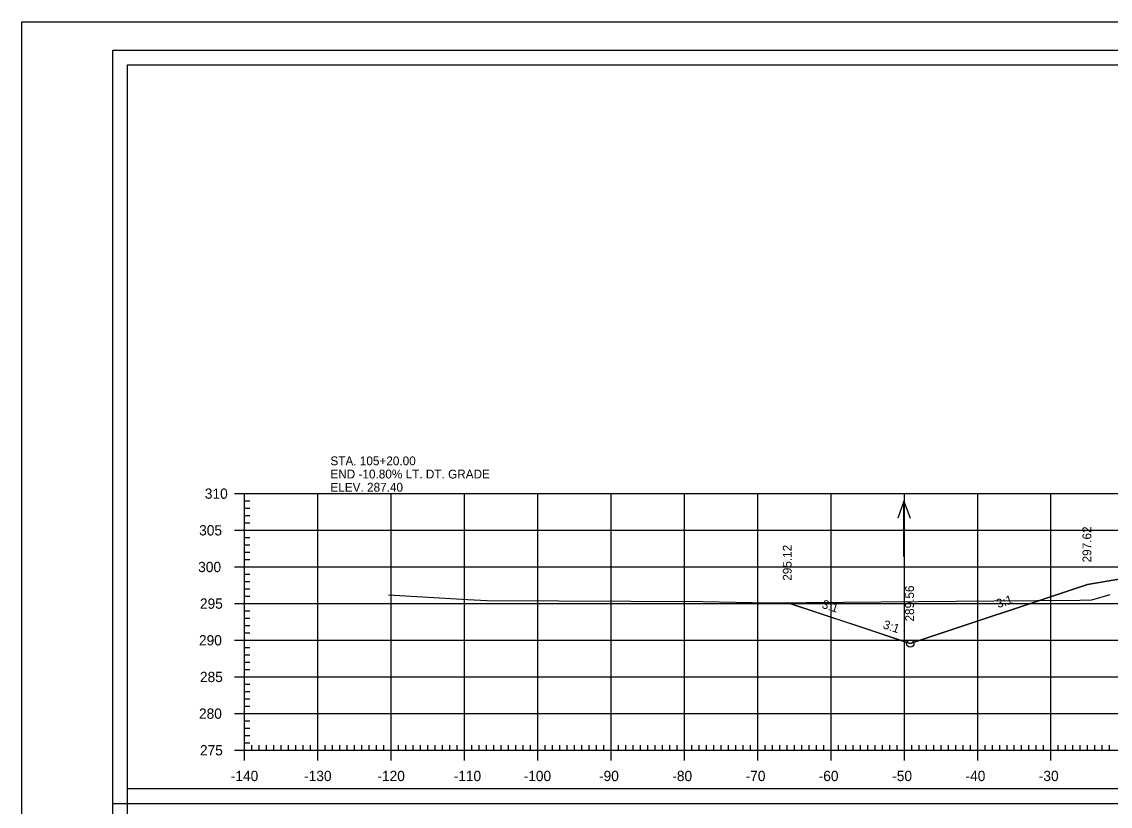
# Model space of a CAD drawing. Extents: x 1368713 to 1370673, y 380279 to 380950.
# Drawn here: x 1369981.9 to 1370130.4, y 380416.8 to 380523.8 of the extents above; entities that cross this region are included whole.
import ezdxf

# ---------------------------------------------------------------- set-up
doc = ezdxf.new("R2010")
doc.units = 0
for name, color, linetype in [('Notes', 7, 'Continuous'), ('R_Alt Surface', 7, 'Continuous'), ('R_Axis', 7, 'Continuous'), ('R_Axis Annot', 7, 'Continuous'), ('R_Border', 7, 'Continuous'), ('R_Border Plan-Plan', 7, 'Continuous'), ('R_Exist Surface', 7, 'Continuous'), ('R_Fin Surface', 7, 'Continuous'), ('R_Grid', 7, 'Continuous'), ('R_No Plot', 7, 'Continuous'), ('R_Water Annot', 7, 'Continuous'), ('R_Xsect Elev', 7, 'Continuous'), ('R_Xsect Slope', 7, 'Continuous')]:
    doc.layers.add(name, color=color, linetype=linetype)

msp = doc.modelspace()

# ---------------------------------------------------------------- linework, layer by layer
at = {"layer": 'R_Alt Surface'}
for points in [[(1370137.28, 380448.71), (1370127.28, 380447.04)], [(1370127.28, 380447.04), (1370103.09, 380438.98)], [(1370103.09, 380438.98), (1370103.09, 380438.98), (1370086.4, 380444.54)]]:
    msp.add_lwpolyline(points, dxfattribs=at)
at = {"layer": 'R_Axis'}
for p, q in [((1370010.88, 380459.42), (1370013.68, 380459.42)), ((1370012.28, 380424.42), (1370012.28, 380459.42)), ((1370012.28, 380458.42), (1370012.98, 380458.42)), ((1370012.28, 380457.42), (1370012.98, 380457.42)), ((1370012.28, 380456.42), (1370012.98, 380456.42)), ((1370012.28, 380455.42), (1370012.98, 380455.42)), ((1370010.88, 380454.42), (1370013.68, 380454.42)), ((1370012.28, 380453.42), (1370012.98, 380453.42)), ((1370012.28, 380452.42), (1370012.98, 380452.42)), ((1370012.28, 380451.42), (1370012.98, 380451.42)), ((1370010.88, 380449.42), (1370013.68, 380449.42)), ((1370012.28, 380450.42), (1370012.98, 380450.42)), ((1370012.28, 380448.42), (1370012.98, 380448.42)), ((1370012.28, 380447.42), (1370012.98, 380447.42)), ((1370012.28, 380446.42), (1370012.98, 380446.42)), ((1370012.28, 380445.42), (1370012.98, 380445.42)), ((1370010.88, 380444.42), (1370013.68, 380444.42)), ((1370012.28, 380443.42), (1370012.98, 380443.42)), ((1370012.28, 380442.42), (1370012.98, 380442.42)), ((1370012.28, 380441.42), (1370012.98, 380441.42)), ((1370010.88, 380439.42), (1370013.68, 380439.42)), ((1370012.28, 380440.42), (1370012.98, 380440.42)), ((1370012.28, 380438.42), (1370012.98, 380438.42)), ((1370012.28, 380437.42), (1370012.98, 380437.42)), ((1370012.28, 380436.42), (1370012.98, 380436.42)), ((1370012.28, 380435.42), (1370012.98, 380435.42)), ((1370010.88, 380434.42), (1370013.68, 380434.42)), ((1370012.28, 380433.42), (1370012.98, 380433.42)), ((1370012.28, 380432.42), (1370012.98, 380432.42)), ((1370012.28, 380431.42), (1370012.98, 380431.42)), ((1370012.28, 380430.42), (1370012.98, 380430.42)), ((1370010.88, 380429.42), (1370013.68, 380429.42)), ((1370012.28, 380428.42), (1370012.98, 380428.42)), ((1370012.28, 380427.42), (1370012.98, 380427.42)), ((1370012.28, 380426.42), (1370012.98, 380426.42)), ((1370012.28, 380423.02), (1370012.28, 380425.82)), ((1370022.28, 380423.02), (1370022.28, 380425.82)), ((1370032.28, 380423.02), (1370032.28, 380425.82)), ((1370042.28, 380423.02), (1370042.28, 380425.82)), ((1370052.28, 380423.02), (1370052.28, 380425.82)), ((1370062.28, 380423.02), (1370062.28, 380425.82)), ((1370072.28, 380423.02), (1370072.28, 380425.82)), ((1370082.28, 380423.02), (1370082.28, 380425.82)), ((1370092.28, 380423.02), (1370092.28, 380425.82)), ((1370102.28, 380423.02), (1370102.28, 380425.82)), ((1370112.28, 380423.02), (1370112.28, 380425.82)), ((1370122.28, 380423.02), (1370122.28, 380425.82)), ((1370010.88, 380424.42), (1370013.68, 380424.42)), ((1370012.28, 380425.42), (1370012.98, 380425.42)), ((1370012.28, 380424.42), (1370292.28, 380424.42)), ((1370013.28, 380424.42), (1370013.28, 380425.12)), ((1370014.28, 380424.42), (1370014.28, 380425.12)), ((1370015.28, 380424.42), (1370015.28, 380425.12)), ((1370016.28, 380424.42), (1370016.28, 380425.12)), ((1370017.28, 380424.42), (1370017.28, 380425.12)), ((1370018.28, 380424.42), (1370018.28, 380425.12)), ((1370019.28, 380424.42), (1370019.28, 380425.12)), ((1370020.28, 380424.42), (1370020.28, 380425.12)), ((1370021.28, 380424.42), (1370021.28, 380425.12)), ((1370023.28, 380424.42), (1370023.28, 380425.12)), ((1370024.28, 380424.42), (1370024.28, 380425.12)), ((1370025.28, 380424.42), (1370025.28, 380425.12)), ((1370026.28, 380424.42), (1370026.28, 380425.12)), ((1370027.28, 380424.42), (1370027.28, 380425.12)), ((1370028.28, 380424.42), (1370028.28, 380425.12)), ((1370029.28, 380424.42), (1370029.28, 380425.12)), ((1370030.28, 380424.42), (1370030.28, 380425.12)), ((1370031.28, 380424.42), (1370031.28, 380425.12)), ((1370033.28, 380424.42), (1370033.28, 380425.12)), ((1370034.28, 380424.42), (1370034.28, 380425.12)), ((1370035.28, 380424.42), (1370035.28, 380425.12)), ((1370036.28, 380424.42), (1370036.28, 380425.12)), ((1370037.28, 380424.42), (1370037.28, 380425.12)), ((1370038.28, 380424.42), (1370038.28, 380425.12)), ((1370039.28, 380424.42), (1370039.28, 380425.12)), ((1370040.28, 380424.42), (1370040.28, 380425.12)), ((1370041.28, 380424.42), (1370041.28, 380425.12)), ((1370043.28, 380424.42), (1370043.28, 380425.12)), ((1370044.28, 380424.42), (1370044.28, 380425.12)), ((1370045.28, 380424.42), (1370045.28, 380425.12)), ((1370046.28, 380424.42), (1370046.28, 380425.12)), ((1370047.28, 380424.42), (1370047.28, 380425.12)), ((1370048.28, 380424.42), (1370048.28, 380425.12)), ((1370049.28, 380424.42), (1370049.28, 380425.12)), ((1370050.28, 380424.42), (1370050.28, 380425.12)), ((1370051.28, 380424.42), (1370051.28, 380425.12)), ((1370053.28, 380424.42), (1370053.28, 380425.12)), ((1370054.28, 380424.42), (1370054.28, 380425.12)), ((1370055.28, 380424.42), (1370055.28, 380425.12)), ((1370056.28, 380424.42), (1370056.28, 380425.12)), ((1370057.28, 380424.42), (1370057.28, 380425.12)), ((1370058.28, 380424.42), (1370058.28, 380425.12)), ((1370059.28, 380424.42), (1370059.28, 380425.12)), ((1370060.28, 380424.42), (1370060.28, 380425.12)), ((1370061.28, 380424.42), (1370061.28, 380425.12)), ((1370063.28, 380424.42), (1370063.28, 380425.12)), ((1370064.28, 380424.42), (1370064.28, 380425.12)), ((1370065.28, 380424.42), (1370065.28, 380425.12)), ((1370066.28, 380424.42), (1370066.28, 380425.12)), ((1370067.28, 380424.42), (1370067.28, 380425.12)), ((1370068.28, 380424.42), (1370068.28, 380425.12)), ((1370069.28, 380424.42), (1370069.28, 380425.12)), ((1370070.28, 380424.42), (1370070.28, 380425.12)), ((1370071.28, 380424.42), (1370071.28, 380425.12)), ((1370073.28, 380424.42), (1370073.28, 380425.12)), ((1370074.28, 380424.42), (1370074.28, 380425.12)), ((1370075.28, 380424.42), (1370075.28, 380425.12)), ((1370076.28, 380424.42), (1370076.28, 380425.12)), ((1370077.28, 380424.42), (1370077.28, 380425.12)), ((1370078.28, 380424.42), (1370078.28, 380425.12)), ((1370079.28, 380424.42), (1370079.28, 380425.12)), ((1370080.28, 380424.42), (1370080.28, 380425.12)), ((1370081.28, 380424.42), (1370081.28, 380425.12)), ((1370083.28, 380424.42), (1370083.28, 380425.12)), ((1370084.28, 380424.42), (1370084.28, 380425.12)), ((1370085.28, 380424.42), (1370085.28, 380425.12)), ((1370086.28, 380424.42), (1370086.28, 380425.12)), ((1370087.28, 380424.42), (1370087.28, 380425.12)), ((1370088.28, 380424.42), (1370088.28, 380425.12)), ((1370089.28, 380424.42), (1370089.28, 380425.12)), ((1370090.28, 380424.42), (1370090.28, 380425.12)), ((1370091.28, 380424.42), (1370091.28, 380425.12)), ((1370093.28, 380424.42), (1370093.28, 380425.12)), ((1370094.28, 380424.42), (1370094.28, 380425.12)), ((1370095.28, 380424.42), (1370095.28, 380425.12)), ((1370096.28, 380424.42), (1370096.28, 380425.12)), ((1370097.28, 380424.42), (1370097.28, 380425.12)), ((1370098.28, 380424.42), (1370098.28, 380425.12)), ((1370099.28, 380424.42), (1370099.28, 380425.12)), ((1370100.28, 380424.42), (1370100.28, 380425.12)), ((1370101.28, 380424.42), (1370101.28, 380425.12)), ((1370103.28, 380424.42), (1370103.28, 380425.12)), ((1370104.28, 380424.42), (1370104.28, 380425.12)), ((1370105.28, 380424.42), (1370105.28, 380425.12)), ((1370106.28, 380424.42), (1370106.28, 380425.12)), ((1370107.28, 380424.42), (1370107.28, 380425.12)), ((1370108.28, 380424.42), (1370108.28, 380425.12)), ((1370109.28, 380424.42), (1370109.28, 380425.12)), ((1370110.28, 380424.42), (1370110.28, 380425.12)), ((1370111.28, 380424.42), (1370111.28, 380425.12)), ((1370113.28, 380424.42), (1370113.28, 380425.12)), ((1370114.28, 380424.42), (1370114.28, 380425.12)), ((1370115.28, 380424.42), (1370115.28, 380425.12)), ((1370116.28, 380424.42), (1370116.28, 380425.12)), ((1370117.28, 380424.42), (1370117.28, 380425.12)), ((1370118.28, 380424.42), (1370118.28, 380425.12)), ((1370119.28, 380424.42), (1370119.28, 380425.12)), ((1370120.28, 380424.42), (1370120.28, 380425.12)), ((1370121.28, 380424.42), (1370121.28, 380425.12)), ((1370123.28, 380424.42), (1370123.28, 380425.12)), ((1370124.28, 380424.42), (1370124.28, 380425.12)), ((1370125.28, 380424.42), (1370125.28, 380425.12)), ((1370126.28, 380424.42), (1370126.28, 380425.12)), ((1370127.28, 380424.42), (1370127.28, 380425.12)), ((1370128.28, 380424.42), (1370128.28, 380425.12)), ((1370129.28, 380424.42), (1370129.28, 380425.12)), ((1370130.28, 380424.42), (1370130.28, 380425.12))]:
    msp.add_line(p, q, dxfattribs=at)
at = {"layer": 'R_Border'}
for p, q in [((1369994.28, 380519.88), (1370310.46, 380519.88)), ((1369994.28, 380314.42), (1369994.28, 380519.88))]:
    msp.add_line(p, q, dxfattribs=at)
at = {"layer": 'R_Border Plan-Plan'}
msp.add_line((1369994.28, 380417.15), (1370310.46, 380417.15), dxfattribs=at)
at = {"layer": 'R_Exist Surface'}
msp.add_lwpolyline([(1370031.89, 380445.61), (1370042.73, 380445), (1370045.33, 380444.85), (1370074.8, 380444.7), (1370083.75, 380444.52), (1370114.49, 380444.78), (1370126.23, 380444.89), (1370127.85, 380444.92), (1370130.37, 380445.68)], dxfattribs=at)
at = {"layer": 'R_Fin Surface'}
msp.add_lwpolyline([(1370086.4, 380444.54), (1370095.2, 380441.62), (1370103.09, 380438.98), (1370127.28, 380447.04), (1370130.44, 380447.57), (1370137.28, 380448.71), (1370141.28, 380448.87), (1370152.28, 380449.09), (1370163.28, 380448.87), (1370167.28, 380448.71), (1370174.12, 380447.57), (1370177.28, 380447.04), (1370199.31, 380439.7), (1370205.6, 380441.81), (1370213.3, 380444.36)], dxfattribs=at)
at = {"layer": 'R_Grid'}
for p, q in [((1370012.28, 380459.42), (1370292.28, 380459.42)), ((1370012.28, 380424.42), (1370012.28, 380459.42)), ((1370022.28, 380424.42), (1370022.28, 380459.42)), ((1370032.28, 380424.42), (1370032.28, 380459.42)), ((1370042.28, 380424.42), (1370042.28, 380459.42)), ((1370052.28, 380424.42), (1370052.28, 380459.42)), ((1370062.28, 380424.42), (1370062.28, 380459.42)), ((1370072.28, 380424.42), (1370072.28, 380459.42)), ((1370082.28, 380424.42), (1370082.28, 380459.42)), ((1370092.28, 380424.42), (1370092.28, 380459.42)), ((1370102.28, 380424.42), (1370102.28, 380459.42)), ((1370112.28, 380424.42), (1370112.28, 380459.42)), ((1370122.28, 380424.42), (1370122.28, 380459.42)), ((1370012.28, 380454.42), (1370292.28, 380454.42)), ((1370012.28, 380449.42), (1370292.28, 380449.42)), ((1370012.28, 380444.42), (1370292.28, 380444.42)), ((1370012.28, 380439.42), (1370292.28, 380439.42)), ((1370012.28, 380434.42), (1370292.28, 380434.42)), ((1370012.28, 380429.42), (1370292.28, 380429.42)), ((1370012.28, 380424.42), (1370292.28, 380424.42))]:
    msp.add_line(p, q, dxfattribs=at)
at = {"layer": 'R_No Plot'}
for points in [[(1369981.88, 380523.77), (1370315.22, 380523.77), (1370315.22, 380310.43), (1369981.88, 380310.43)], [(1370308.46, 380419.15), (1369996.28, 380419.15), (1369996.28, 380517.88), (1370245.82, 380517.88), (1370245.82, 380508), (1370263.36, 380508), (1370287.46, 380508), (1370287.46, 380485.66), (1370308.46, 380485.66)], [(1369996.28, 380517.88), (1370245.82, 380517.88), (1370245.82, 380508), (1370263.36, 380508), (1370287.46, 380508), (1370287.46, 380485.66), (1370308.46, 380485.66), (1370308.46, 380316.42), (1369996.28, 380316.42)]]:
    msp.add_lwpolyline(points, close=True, dxfattribs=at)
msp.add_circle((1370103.09, 380438.98), 0.5, dxfattribs=at)
at = {"layer": 'R_Water Annot'}
for p, q in [((1370102.21, 380458.4), (1370101.37, 380456.09)), ((1370102.21, 380450.86), (1370102.21, 380458.4)), ((1370102.21, 380458.4), (1370103.05, 380456.09))]:
    msp.add_line(p, q, dxfattribs=at)

# ---------------------------------------------------------------- texts
at = {"layer": 'Notes'}
for s, p in [('STA. 105+20.00', (1370023.98, 380463.29)), ('END -10.80% LT. DT. GRADE', (1370023.98, 380461.49)), ('ELEV. 287.40', (1370023.98, 380459.69))]:
    msp.add_text(s, height=1.2, dxfattribs=at).set_placement(p)
at = {"layer": 'R_Axis Annot'}
for s, p in [('310', (1370006.85, 380458.72)), ('305', (1370006.07, 380453.72)), ('300', (1370005.94, 380448.72)), ('295', (1370006.18, 380443.72)), ('290', (1370006.05, 380438.72)), ('285', (1370006.18, 380433.72)), ('280', (1370006.05, 380428.72)), ('275', (1370006.18, 380423.72)), ('-140', (1370010.39, 380420.22)), ('-130', (1370020.39, 380420.22)), ('-120', (1370030.39, 380420.22)), ('-110', (1370040.79, 380420.22)), ('-100', (1370050.34, 380420.22)), ('-90', (1370060.62, 380420.22)), ('-80', (1370070.62, 380420.22)), ('-70', (1370080.62, 380420.22)), ('-60', (1370090.59, 380420.22)), ('-50', (1370100.62, 380420.22)), ('-40', (1370110.62, 380420.22)), ('-30', (1370120.62, 380420.22))]:
    msp.add_text(s, height=1.4, dxfattribs=at).set_placement(p)
at = {"layer": 'R_Xsect Elev'}
for s, p in [('297.62', (1370127.78, 380450.04)), ('295.12', (1370086.9, 380447.54)), ('289.56', (1370103.59, 380441.98))]:
    msp.add_text(s, height=1.2, rotation=90, dxfattribs=at).set_placement(p)
at = {"layer": 'R_Xsect Slope'}
for rotation, p in [(341.6689, (1370090.93, 380443.86)), (18.4349, (1370115.06, 380443.79)), (341.4495, (1370099.27, 380441.08))]:
    msp.add_text('3:1', height=1.2, rotation=rotation, dxfattribs=at).set_placement(p)

doc.saveas('drawing.dxf')
